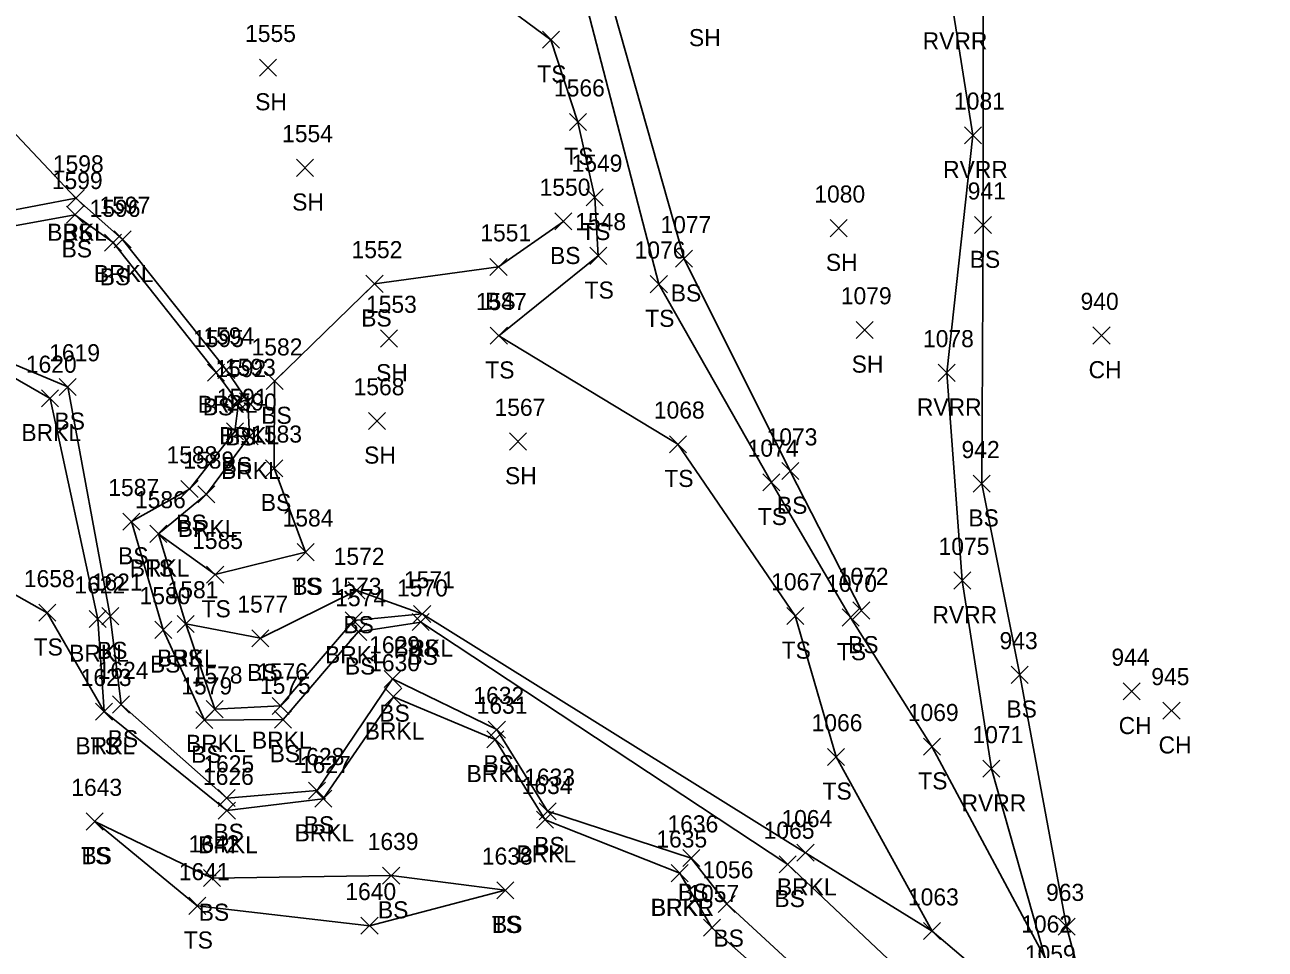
# Model space of a CAD drawing. Extents: x 1885914 to 1887218, y 756253 to 760620.
# Drawn here: x 1886519.5 to 1886664.7, y 759655 to 759763.2 of the extents above; entities that cross this region are included whole.
import ezdxf

# ---------------------------------------------------------------- set-up
doc = ezdxf.new("R2010")
doc.units = 0
for name, color, linetype in [('L_A', 7, 'Continuous'), ('L_I', 7, 'Continuous'), ('L_TIC', 7, 'Continuous'), ('LAWE', 7, 'Continuous'), ('LELB', 7, 'Continuous')]:
    doc.layers.add(name, color=color, linetype=linetype)

msp = doc.modelspace()

# ---------------------------------------------------------------- linework, layer by layer
at = {"layer": 'L_TIC'}
for points in [[(1886580.11, 759760.41), (1886582.11, 759762.41)], [(1886582.11, 759760.41), (1886580.11, 759762.41)], [(1886547.01, 759757.15), (1886549.01, 759759.15)], [(1886549.01, 759757.15), (1886547.01, 759759.15)], [(1886583.27, 759750.77), (1886585.27, 759752.77)], [(1886585.27, 759750.77), (1886583.27, 759752.77)], [(1886583.27, 759750.77), (1886585.27, 759752.77)], [(1886585.27, 759750.77), (1886583.27, 759752.77)], [(1886629.5, 759749.23), (1886631.5, 759751.23)], [(1886631.5, 759749.23), (1886629.5, 759751.23)], [(1886551.34, 759745.42), (1886553.34, 759747.42)], [(1886553.34, 759745.42), (1886551.34, 759747.42)], [(1886524.52, 759741.88), (1886526.52, 759743.88)], [(1886526.52, 759741.88), (1886524.52, 759743.88)], [(1886524.52, 759741.88), (1886526.52, 759743.88)], [(1886526.52, 759741.88), (1886524.52, 759743.88)], [(1886585.24, 759741.96), (1886587.24, 759743.96)], [(1886587.24, 759741.96), (1886585.24, 759743.96)], [(1886524.4, 759739.93), (1886526.4, 759741.93)], [(1886526.4, 759739.93), (1886524.4, 759741.93)], [(1886581.57, 759739.15), (1886583.57, 759741.15)], [(1886583.57, 759739.15), (1886581.57, 759741.15)], [(1886613.8, 759738.35), (1886615.8, 759740.35)], [(1886615.8, 759738.35), (1886613.8, 759740.35)], [(1886630.69, 759738.71), (1886632.69, 759740.71)], [(1886632.69, 759738.71), (1886630.69, 759740.71)], [(1886528.87, 759736.67), (1886530.87, 759738.67)], [(1886530.87, 759736.67), (1886528.87, 759738.67)], [(1886529.98, 759737.04), (1886531.98, 759739.04)], [(1886531.98, 759737.04), (1886529.98, 759739.04)], [(1886585.65, 759735.11), (1886587.65, 759737.11)], [(1886587.65, 759735.11), (1886585.65, 759737.11)], [(1886573.98, 759733.81), (1886575.98, 759735.81)], [(1886575.98, 759733.81), (1886573.98, 759735.81)], [(1886595.7, 759734.77), (1886597.7, 759736.77)], [(1886597.7, 759734.77), (1886595.7, 759736.77)], [(1886559.47, 759731.84), (1886561.47, 759733.84)], [(1886561.47, 759731.84), (1886559.47, 759733.84)], [(1886592.74, 759731.8), (1886594.74, 759733.8)], [(1886594.74, 759731.8), (1886592.74, 759733.8)], [(1886616.82, 759726.44), (1886618.82, 759728.44)], [(1886618.82, 759726.44), (1886616.82, 759728.44)], [(1886561.16, 759725.44), (1886563.16, 759727.44)], [(1886563.16, 759725.44), (1886561.16, 759727.44)], [(1886574.02, 759725.76), (1886576.02, 759727.76)], [(1886576.02, 759725.76), (1886574.02, 759727.76)], [(1886644.55, 759725.79), (1886646.55, 759727.79)], [(1886646.55, 759725.79), (1886644.55, 759727.79)], [(1886540.92, 759721.44), (1886542.92, 759723.44)], [(1886542.92, 759721.44), (1886540.92, 759723.44)], [(1886542.13, 759721.74), (1886544.13, 759723.74)], [(1886544.13, 759721.74), (1886542.13, 759723.74)], [(1886547.77, 759720.45), (1886549.77, 759722.45)], [(1886549.77, 759720.45), (1886547.77, 759722.45)], [(1886626.43, 759721.42), (1886628.43, 759723.42)], [(1886628.43, 759721.42), (1886626.43, 759723.42)], [(1886523.57, 759719.77), (1886525.57, 759721.77)], [(1886525.57, 759719.77), (1886523.57, 759721.77)], [(1886521.49, 759718.43), (1886523.49, 759720.43)], [(1886523.49, 759718.43), (1886521.49, 759720.43)], [(1886543.53, 759717.92), (1886545.53, 759719.92)], [(1886545.53, 759717.92), (1886543.53, 759719.92)], [(1886544.65, 759718.06), (1886546.65, 759720.06)], [(1886546.65, 759718.06), (1886544.65, 759720.06)], [(1886543.13, 759714.56), (1886545.13, 759716.56)], [(1886545.13, 759714.56), (1886543.13, 759716.56)], [(1886559.76, 759715.79), (1886561.76, 759717.79)], [(1886561.76, 759715.79), (1886559.76, 759717.79)], [(1886544.85, 759714), (1886546.85, 759716)], [(1886546.85, 759714), (1886544.85, 759716)], [(1886576.25, 759713.38), (1886578.25, 759715.38)], [(1886578.25, 759713.38), (1886576.25, 759715.38)], [(1886594.98, 759713.06), (1886596.98, 759715.06)], [(1886596.98, 759713.06), (1886594.98, 759715.06)], [(1886547.72, 759710.25), (1886549.72, 759712.25)], [(1886549.72, 759710.25), (1886547.72, 759712.25)], [(1886608.12, 759709.92), (1886610.12, 759711.92)], [(1886610.12, 759709.92), (1886608.12, 759711.92)], [(1886537.81, 759707.82), (1886539.81, 759709.82)], [(1886539.81, 759707.82), (1886537.81, 759709.82)], [(1886605.91, 759708.6), (1886607.91, 759710.6)], [(1886607.91, 759708.6), (1886605.91, 759710.6)], [(1886630.53, 759708.44), (1886632.53, 759710.44)], [(1886632.53, 759708.44), (1886630.53, 759710.44)], [(1886539.79, 759707.21), (1886541.79, 759709.21)], [(1886541.79, 759707.21), (1886539.79, 759709.21)], [(1886531.01, 759704), (1886533.01, 759706)], [(1886533.01, 759704), (1886531.01, 759706)], [(1886534.18, 759702.57), (1886536.18, 759704.57)], [(1886536.18, 759702.57), (1886534.18, 759704.57)], [(1886534.18, 759702.57), (1886536.18, 759704.57)], [(1886536.18, 759702.57), (1886534.18, 759704.57)], [(1886551.4, 759700.43), (1886553.4, 759702.43)], [(1886553.4, 759700.43), (1886551.4, 759702.43)], [(1886551.4, 759700.43), (1886553.4, 759702.43)], [(1886553.4, 759700.43), (1886551.4, 759702.43)], [(1886540.82, 759697.8), (1886542.82, 759699.8)], [(1886542.82, 759697.8), (1886540.82, 759699.8)], [(1886628.25, 759697.11), (1886630.25, 759699.11)], [(1886630.25, 759697.11), (1886628.25, 759699.11)], [(1886557.38, 759695.94), (1886559.38, 759697.94)], [(1886559.38, 759695.94), (1886557.38, 759697.94)], [(1886521.17, 759693.33), (1886523.17, 759695.33)], [(1886523.17, 759693.33), (1886521.17, 759695.33)], [(1886521.17, 759693.33), (1886523.17, 759695.33)], [(1886523.17, 759693.33), (1886521.17, 759695.33)], [(1886528.54, 759692.93), (1886530.54, 759694.93)], [(1886530.54, 759692.93), (1886528.54, 759694.93)], [(1886565.04, 759693.2), (1886567.04, 759695.2)], [(1886567.04, 759693.2), (1886565.04, 759695.2)], [(1886565.04, 759693.2), (1886567.04, 759695.2)], [(1886567.04, 759693.2), (1886565.04, 759695.2)], [(1886608.71, 759692.96), (1886610.71, 759694.96)], [(1886610.71, 759692.96), (1886608.71, 759694.96)], [(1886615.18, 759692.78), (1886617.18, 759694.78)], [(1886617.18, 759692.78), (1886615.18, 759694.78)], [(1886616.45, 759693.6), (1886618.45, 759695.6)], [(1886618.45, 759693.6), (1886616.45, 759695.6)], [(1886527.08, 759692.59), (1886529.08, 759694.59)], [(1886529.08, 759692.59), (1886527.08, 759694.59)], [(1886534.74, 759691.33), (1886536.74, 759693.33)], [(1886536.74, 759691.33), (1886534.74, 759693.33)], [(1886537.38, 759692.03), (1886539.38, 759694.03)], [(1886539.38, 759692.03), (1886537.38, 759694.03)], [(1886537.38, 759692.03), (1886539.38, 759694.03)], [(1886539.38, 759692.03), (1886537.38, 759694.03)], [(1886557.03, 759692.43), (1886559.03, 759694.43)], [(1886559.03, 759692.43), (1886557.03, 759694.43)], [(1886564.88, 759692.24), (1886566.88, 759694.24)], [(1886566.88, 759692.24), (1886564.88, 759694.24)], [(1886546.11, 759690.35), (1886548.11, 759692.35)], [(1886548.11, 759690.35), (1886546.11, 759692.35)], [(1886557.56, 759691.1), (1886559.56, 759693.1)], [(1886559.56, 759691.1), (1886557.56, 759693.1)], [(1886561.59, 759685.58), (1886563.59, 759687.58)], [(1886563.59, 759685.58), (1886561.59, 759687.58)], [(1886634.98, 759686.07), (1886636.98, 759688.07)], [(1886636.98, 759686.07), (1886634.98, 759688.07)], [(1886648.07, 759684.13), (1886650.07, 759686.13)], [(1886650.07, 759684.13), (1886648.07, 759686.13)], [(1886529.8, 759682.59), (1886531.8, 759684.59)], [(1886531.8, 759682.59), (1886529.8, 759684.59)], [(1886561.67, 759683.49), (1886563.67, 759685.49)], [(1886563.67, 759683.49), (1886561.67, 759685.49)], [(1886527.82, 759681.76), (1886529.82, 759683.76)], [(1886529.82, 759681.76), (1886527.82, 759683.76)], [(1886527.82, 759681.76), (1886529.82, 759683.76)], [(1886529.82, 759681.76), (1886527.82, 759683.76)], [(1886540.76, 759682.05), (1886542.76, 759684.05)], [(1886542.76, 759682.05), (1886540.76, 759684.05)], [(1886548.48, 759682.42), (1886550.48, 759684.42)], [(1886550.48, 759682.42), (1886548.48, 759684.42)], [(1886652.74, 759681.86), (1886654.74, 759683.86)], [(1886654.74, 759681.86), (1886652.74, 759683.86)], [(1886539.56, 759680.77), (1886541.56, 759682.77)], [(1886541.56, 759680.77), (1886539.56, 759682.77)], [(1886548.76, 759680.84), (1886550.76, 759682.84)], [(1886550.76, 759680.84), (1886548.76, 759682.84)], [(1886573.78, 759679.66), (1886575.78, 759681.66)], [(1886575.78, 759679.66), (1886573.78, 759681.66)], [(1886573.6, 759678.51), (1886575.6, 759680.51)], [(1886575.6, 759678.51), (1886573.6, 759680.51)], [(1886624.7, 759677.66), (1886626.7, 759679.66)], [(1886626.7, 759677.66), (1886624.7, 759679.66)], [(1886613.49, 759676.46), (1886615.49, 759678.46)], [(1886615.49, 759676.46), (1886613.49, 759678.46)], [(1886631.66, 759675.07), (1886633.66, 759677.07)], [(1886633.66, 759675.07), (1886631.66, 759677.07)], [(1886552.74, 759672.51), (1886554.74, 759674.51)], [(1886554.74, 759672.51), (1886552.74, 759674.51)], [(1886542.17, 759671.64), (1886544.17, 759673.64)], [(1886544.17, 759671.64), (1886542.17, 759673.64)], [(1886553.47, 759671.57), (1886555.47, 759673.57)], [(1886555.47, 759671.57), (1886553.47, 759673.57)], [(1886542.18, 759670.18), (1886544.18, 759672.18)], [(1886544.18, 759670.18), (1886542.18, 759672.18)], [(1886579.72, 759670.09), (1886581.72, 759672.09)], [(1886581.72, 759670.09), (1886579.72, 759672.09)], [(1886526.72, 759668.9), (1886528.72, 759670.9)], [(1886528.72, 759668.9), (1886526.72, 759670.9)], [(1886526.72, 759668.9), (1886528.72, 759670.9)], [(1886528.72, 759668.9), (1886526.72, 759670.9)], [(1886579.43, 759669.11), (1886581.43, 759671.11)], [(1886581.43, 759669.11), (1886579.43, 759671.11)], [(1886609.91, 759665.24), (1886611.91, 759667.24)], [(1886611.91, 759665.24), (1886609.91, 759667.24)], [(1886596.54, 759664.62), (1886598.54, 759666.62)], [(1886598.54, 759664.62), (1886596.54, 759666.62)], [(1886596.54, 759664.62), (1886598.54, 759666.62)], [(1886598.54, 759664.62), (1886596.54, 759666.62)], [(1886607.83, 759663.88), (1886609.83, 759665.88)], [(1886609.83, 759663.88), (1886607.83, 759665.88)], [(1886540.45, 759662.28), (1886542.45, 759664.28)], [(1886542.45, 759662.28), (1886540.45, 759664.28)], [(1886561.42, 759662.56), (1886563.42, 759664.56)], [(1886563.42, 759662.56), (1886561.42, 759664.56)], [(1886595.19, 759662.85), (1886597.19, 759664.85)], [(1886597.19, 759662.85), (1886595.19, 759664.85)], [(1886595.19, 759662.85), (1886597.19, 759664.85)], [(1886597.19, 759662.85), (1886595.19, 759664.85)], [(1886574.77, 759660.85), (1886576.77, 759662.85)], [(1886576.77, 759660.85), (1886574.77, 759662.85)], [(1886574.77, 759660.85), (1886576.77, 759662.85)], [(1886576.77, 759660.85), (1886574.77, 759662.85)], [(1886538.73, 759659.03), (1886540.73, 759661.03)], [(1886540.73, 759659.03), (1886538.73, 759661.03)], [(1886600.69, 759659.25), (1886602.69, 759661.25)], [(1886602.69, 759659.25), (1886600.69, 759661.25)], [(1886558.88, 759656.7), (1886560.88, 759658.7)], [(1886560.88, 759656.7), (1886558.88, 759658.7)], [(1886598.96, 759656.47), (1886600.96, 759658.47)], [(1886600.96, 759656.47), (1886598.96, 759658.47)], [(1886640.47, 759656.6), (1886642.47, 759658.6)], [(1886642.47, 759656.6), (1886640.47, 759658.6)], [(1886624.72, 759656.07), (1886626.72, 759658.07)], [(1886626.72, 759656.07), (1886624.72, 759658.07)], [(1886624.72, 759656.07), (1886626.72, 759658.07)], [(1886626.72, 759656.07), (1886624.72, 759658.07)]]:
    msp.add_lwpolyline(points, dxfattribs=at)
at = {"layer": 'LAWE'}
for points in [[(1886640.49, 759642.77), (1886639.36, 759650.41), (1886638.96, 759653.9), (1886632.66, 759676.07), (1886629.25, 759698.11), (1886627.43, 759722.42), (1886630.5, 759750.23), (1886628.11, 759765.28), (1886627.09, 759783.44), (1886625.27, 759802.03), (1886629.52, 759812.91), (1886630.27, 759842.49), (1886632.62, 759860.26), (1886629.59, 759874.2), (1886633.72, 759902.05), (1886645.92, 759929.12), (1886643.57, 759950.66), (1886647.93, 759967.68)], [(1886640.49, 759642.77), (1886635.93, 759648.39), (1886625.72, 759657.07), (1886610.91, 759666.24), (1886566.04, 759694.2), (1886558.03, 759693.43), (1886549.48, 759683.42), (1886541.76, 759683.05), (1886538.38, 759693.03), (1886535.18, 759703.57), (1886540.79, 759708.21), (1886545.85, 759715), (1886545.65, 759719.06), (1886543.13, 759722.74), (1886530.98, 759738.04), (1886525.52, 759742.88), (1886512.03, 759740.29)], [(1886513.99, 759724.28), (1886522.49, 759719.43), (1886528.08, 759693.59), (1886528.82, 759682.76), (1886543.18, 759671.18), (1886554.47, 759672.57), (1886562.67, 759684.49), (1886574.6, 759679.51), (1886580.43, 759670.11), (1886596.19, 759663.85)], [(1886641.69, 759620.32), (1886638.77, 759624.39), (1886634.13, 759631.53), (1886624.26, 759635.97), (1886599.96, 759657.47), (1886596.19, 759663.85)]]:
    msp.add_lwpolyline(points, dxfattribs=at)
at = {"layer": 'LELB'}
for points in [[(1886651.59, 759963.58), (1886647.85, 759929.2), (1886639.89, 759913.67), (1886633.14, 759883.1), (1886633.96, 759851.09), (1886632.16, 759822.61), (1886631.66, 759800.6), (1886631.69, 759739.71), (1886631.53, 759709.44), (1886635.98, 759687.07), (1886641.47, 759657.6), (1886645.02, 759644.27), (1886643.52, 759637.8), (1886640.86, 759635.28), (1886641.28, 759631.71), (1886642.18, 759628.94), (1886648.32, 759617.92), (1886654.14, 759597.23), (1886659.93, 759557.18), (1886668.26, 759522.06), (1886683.34, 759437.14), (1886685.68, 759384.91)], [(1886617.45, 759694.6), (1886609.12, 759710.92), (1886596.7, 759735.77), (1886587.3, 759769), (1886583.62, 759785.07), (1886576.89, 759804.45), (1886570.9, 759822.79), (1886567.51, 759854.62), (1886567.73, 759883.17), (1886571, 759906.61), (1886569.47, 759932.79), (1886578.55, 759960.06)], [(1886491.13, 759804.2), (1886501.13, 759810.72), (1886522.18, 759805.09), (1886544.57, 759789.63), (1886568.21, 759770.94), (1886581.11, 759761.41), (1886584.27, 759751.77)], [(1886638.96, 759653.9), (1886625.7, 759678.66), (1886616.18, 759693.78), (1886606.91, 759709.6), (1886593.74, 759732.8), (1886584.57, 759768.2), (1886579.84, 759785.39)], [(1886525.52, 759742.88), (1886510.94, 759758.31)], [(1886625.72, 759657.07), (1886614.49, 759677.46), (1886609.71, 759693.96), (1886595.98, 759714.06), (1886575.02, 759726.76), (1886586.65, 759736.11), (1886586.24, 759742.96), (1886584.27, 759751.77)], [(1886640.86, 759635.28), (1886629.46, 759645.39), (1886608.83, 759664.88), (1886565.88, 759693.24), (1886558.56, 759692.1), (1886549.76, 759681.84), (1886540.56, 759681.77), (1886535.74, 759692.33), (1886532.01, 759705), (1886538.81, 759708.82), (1886544.13, 759715.56), (1886544.53, 759718.92), (1886541.92, 759722.44), (1886529.87, 759737.67), (1886525.4, 759740.93), (1886512.72, 759738.63)], [(1886582.57, 759740.15), (1886574.98, 759734.81), (1886560.47, 759732.84), (1886548.77, 759721.45), (1886548.72, 759711.25), (1886552.4, 759701.43)], [(1886512.44, 759725.86), (1886524.57, 759720.77), (1886529.54, 759693.93), (1886530.8, 759683.59), (1886543.17, 759672.64), (1886553.74, 759673.51), (1886562.59, 759686.58), (1886574.78, 759680.66), (1886580.72, 759671.09), (1886597.54, 759665.62)], [(1886476.48, 759715.13), (1886490.7, 759710.54), (1886506.3, 759703.27), (1886522.17, 759694.33)], [(1886552.4, 759701.43), (1886541.82, 759698.8), (1886535.18, 759703.57)], [(1886566.04, 759694.2), (1886558.38, 759696.94), (1886547.11, 759691.35), (1886538.38, 759693.03)], [(1886528.82, 759682.76), (1886522.17, 759694.33)], [(1886575.77, 759661.85), (1886562.42, 759663.56), (1886541.45, 759663.28), (1886527.72, 759669.9)], [(1886575.77, 759661.85), (1886559.88, 759657.7), (1886539.73, 759660.03), (1886527.72, 759669.9)], [(1886641.28, 759631.71), (1886625.27, 759638.54), (1886601.69, 759660.25), (1886597.54, 759665.62)]]:
    msp.add_lwpolyline(points, dxfattribs=at)

# ---------------------------------------------------------------- texts
at = {"layer": 'L_A'}
for s, p in [('SH', (1886597.27, 759760.66)), ('RVRR', (1886624.62, 759760.28)), ('TS', (1886579.52, 759756.41)), ('SH', (1886546.5, 759753.15)), ('TS', (1886582.68, 759746.77)), ('TS', (1886582.68, 759746.77)), ('RVRR', (1886627.01, 759745.23)), ('SH', (1886550.83, 759741.42)), ('BRKL', (1886522.16, 759737.88)), ('BS', (1886523.96, 759737.88)), ('TS', (1886584.65, 759737.96)), ('BS', (1886523.84, 759735.93)), ('BS', (1886581.01, 759735.15)), ('SH', (1886613.29, 759734.35)), ('BS', (1886630.13, 759734.71)), ('BRKL', (1886527.62, 759733.04)), ('BS', (1886528.31, 759732.67)), ('TS', (1886585.06, 759731.11)), ('BS', (1886595.14, 759730.77)), ('BS', (1886573.42, 759729.81)), ('BS', (1886558.91, 759727.84)), ('TS', (1886592.15, 759727.8)), ('TS', (1886573.43, 759721.76)), ('SH', (1886616.31, 759722.44)), ('CH', (1886644.04, 759721.79)), ('SH', (1886560.65, 759721.44)), ('BRKL', (1886539.77, 759717.74)), ('BS', (1886540.36, 759717.44)), ('RVRR', (1886623.94, 759717.42)), ('BS', (1886547.21, 759716.45)), ('BS', (1886523.01, 759715.77)), ('BRKL', (1886519.14, 759714.43)), ('BRKL', (1886542.3, 759714.06)), ('BS', (1886542.97, 759713.92)), ('SH', (1886559.25, 759711.79)), ('BS', (1886542.57, 759710.56)), ('BRKL', (1886542.5, 759710)), ('SH', (1886575.74, 759709.38)), ('TS', (1886594.39, 759709.06)), ('BS', (1886547.16, 759706.25)), ('BS', (1886607.56, 759705.92)), ('TS', (1886605.32, 759704.6)), ('BS', (1886629.97, 759704.44)), ('BS', (1886537.25, 759703.82)), ('BRKL', (1886537.44, 759703.21)), ('BS', (1886530.45, 759700)), ('BRKL', (1886531.83, 759698.57)), ('TS', (1886533.59, 759698.57)), ('TS', (1886550.81, 759696.43)), ('BS', (1886550.85, 759696.43)), ('TS', (1886540.23, 759693.8)), ('RVRR', (1886625.76, 759693.11)), ('BS', (1886556.82, 759691.94)), ('TS', (1886520.58, 759689.33)), ('TS', (1886520.58, 759689.33)), ('BRKL', (1886524.73, 759688.59)), ('BS', (1886527.98, 759688.93)), ('BRKL', (1886554.67, 759688.43)), ('BRKL', (1886562.68, 759689.2)), ('BS', (1886564.48, 759689.2)), ('TS', (1886608.12, 759688.96)), ('TS', (1886614.59, 759688.78)), ('BS', (1886615.89, 759689.6)), ('BS', (1886534.19, 759687.33)), ('BRKL', (1886535.02, 759688.03)), ('BS', (1886536.82, 759688.03)), ('BS', (1886557, 759687.1)), ('BS', (1886564.32, 759688.24)), ('BS', (1886545.55, 759686.35)), ('BS', (1886561.03, 759681.58)), ('BS', (1886634.42, 759682.07)), ('CH', (1886647.56, 759680.13)), ('BS', (1886529.24, 759678.59)), ('BRKL', (1886546.12, 759678.42)), ('BRKL', (1886559.32, 759679.49)), ('BRKL', (1886525.47, 759677.76)), ('TS', (1886527.23, 759677.76)), ('BRKL', (1886538.41, 759678.05)), ('BS', (1886539, 759676.77)), ('BS', (1886548.2, 759676.84)), ('CH', (1886652.23, 759677.86)), ('BS', (1886573.22, 759675.66)), ('BRKL', (1886571.24, 759674.51)), ('TS', (1886612.9, 759672.46)), ('TS', (1886624.11, 759673.66)), ('RVRR', (1886629.17, 759671.07)), ('BS', (1886552.18, 759668.51)), ('BS', (1886541.61, 759667.64)), ('BRKL', (1886551.11, 759667.57)), ('BRKL', (1886539.83, 759666.18)), ('BS', (1886579.16, 759666.09)), ('TS', (1886526.13, 759664.9)), ('BS', (1886526.16, 759664.9)), ('BRKL', (1886577.08, 759665.11)), ('BRKL', (1886607.56, 759661.24)), ('BS', (1886595.98, 759660.62)), ('BS', (1886595.98, 759660.62)), ('BS', (1886607.27, 759659.88)), ('BS', (1886539.89, 759658.28)), ('BS', (1886560.86, 759658.56)), ('BRKR', (1886592.78, 759658.85)), ('BRKL', (1886592.83, 759658.85)), ('TS', (1886574.18, 759656.85)), ('BS', (1886574.21, 759656.85)), ('TS', (1886538.14, 759655.03)), ('BS', (1886600.13, 759655.25))]:
    msp.add_text(s, height=2, dxfattribs=at).set_placement(p)
at = {"layer": 'L_I'}
for s, p in [('1555', (1886545.32, 759761.15)), ('1566', (1886581.47, 759754.77)), ('1566', (1886581.47, 759754.77)), ('1081', (1886628.29, 759753.23)), ('1554', (1886549.65, 759749.42)), ('1598', (1886522.82, 759745.88)), ('1598', (1886522.82, 759745.88)), ('1549', (1886583.53, 759745.96)), ('1599', (1886522.7, 759743.93)), ('1550', (1886579.79, 759743.15)), ('1080', (1886611.94, 759742.35)), ('941', (1886629.89, 759742.71)), ('1596', (1886527.12, 759740.67)), ('1597', (1886528.28, 759741.04)), ('1551', (1886572.85, 759737.81)), ('1548', (1886583.96, 759739.11)), ('1077', (1886593.93, 759738.77)), ('1552', (1886557.78, 759735.84)), ('1076', (1886590.91, 759735.8)), ('1079', (1886615.04, 759730.44)), ('1553', (1886559.47, 759729.44)), ('1547', (1886572.33, 759729.76)), ('940', (1886643.1, 759729.79)), ('1595', (1886539.23, 759725.44)), ('1594', (1886540.44, 759725.74)), ('1078', (1886624.66, 759725.42)), ('1619', (1886522.39, 759723.77)), ('1582', (1886546.08, 759724.45)), ('1620', (1886519.66, 759722.43)), ('1592', (1886541.84, 759721.92)), ('1593', (1886542.96, 759722.06)), ('1568', (1886558.02, 759719.79)), ('1591', (1886542, 759718.56)), ('1590', (1886543.07, 759718)), ('1567', (1886574.51, 759717.38)), ('1068', (1886593.16, 759717.06)), ('1583', (1886546.03, 759714.25)), ('1073', (1886606.35, 759713.92)), ('1588', (1886536.12, 759711.82)), ('1074', (1886604.14, 759712.6)), ('942', (1886629.17, 759712.44)), ('1589', (1886538.09, 759711.21)), ('1587', (1886529.31, 759708)), ('1586', (1886532.43, 759706.57)), ('1586', (1886532.43, 759706.57)), ('1584', (1886549.71, 759704.43)), ('1584', (1886549.71, 759704.43)), ('1585', (1886539.12, 759701.8)), ('1572', (1886555.69, 759699.94)), ('1075', (1886626.48, 759701.11)), ('1658', (1886519.43, 759697.33)), ('1658', (1886519.43, 759697.33)), ('1571', (1886563.91, 759697.2)), ('1571', (1886563.91, 759697.2)), ('1072', (1886614.68, 759697.6)), ('1622', (1886525.34, 759696.59)), ('1621', (1886527.37, 759696.93)), ('1581', (1886536.25, 759696.03)), ('1581', (1886536.25, 759696.03)), ('1573', (1886555.33, 759696.43)), ('1570', (1886563.1, 759696.24)), ('1067', (1886606.89, 759696.96)), ('1070', (1886613.32, 759696.78)), ('1580', (1886532.97, 759695.33)), ('1577', (1886544.41, 759694.35)), ('1574', (1886555.87, 759695.1)), ('943', (1886633.62, 759690.07)), ('1629', (1886559.84, 759689.58)), ('1630', (1886559.84, 759687.49)), ('944', (1886646.71, 759688.13)), ('1623', (1886526.08, 759685.76)), ('1623', (1886526.08, 759685.76)), ('1624', (1886528.06, 759686.59)), ('1578', (1886539.07, 759686.05)), ('1576', (1886546.73, 759686.42)), ('945', (1886651.38, 759685.86)), ('1579', (1886537.86, 759684.77)), ('1575', (1886547.06, 759684.84)), ('1632', (1886572.04, 759683.66)), ('1631', (1886572.42, 759682.51)), ('1069', (1886622.88, 759681.66)), ('1066', (1886611.62, 759680.46)), ('1071', (1886630.45, 759679.07)), ('1625', (1886540.43, 759675.64)), ('1628', (1886550.99, 759676.51)), ('1627', (1886551.73, 759675.57)), ('1626', (1886540.39, 759674.18)), ('1633', (1886577.98, 759674.09)), ('1643', (1886524.98, 759672.9)), ('1643', (1886524.98, 759672.9)), ('1634', (1886577.69, 759673.11)), ('1636', (1886594.75, 759668.62)), ('1636', (1886594.75, 759668.62)), ('1064', (1886608.09, 759669.24)), ('1639', (1886559.67, 759666.56)), ('1635', (1886593.45, 759666.85)), ('1635', (1886593.45, 759666.85)), ('1065', (1886606.01, 759667.88)), ('1642', (1886538.71, 759666.28)), ('1638', (1886573.03, 759664.85)), ('1638', (1886573.03, 759664.85)), ('1641', (1886537.56, 759663.03)), ('1056', (1886598.86, 759663.25)), ('1640', (1886557.05, 759660.7)), ('1057', (1886597.19, 759660.47)), ('1063', (1886622.9, 759660.07)), ('1063', (1886622.9, 759660.07)), ('963', (1886639.06, 759660.6)), ('1062', (1886636.15, 759656.9)), ('1062', (1886636.15, 759656.9)), ('1059', (1886636.58, 759653.41))]:
    msp.add_text(s, height=2, dxfattribs=at).set_placement(p)

doc.saveas('drawing.dxf')
